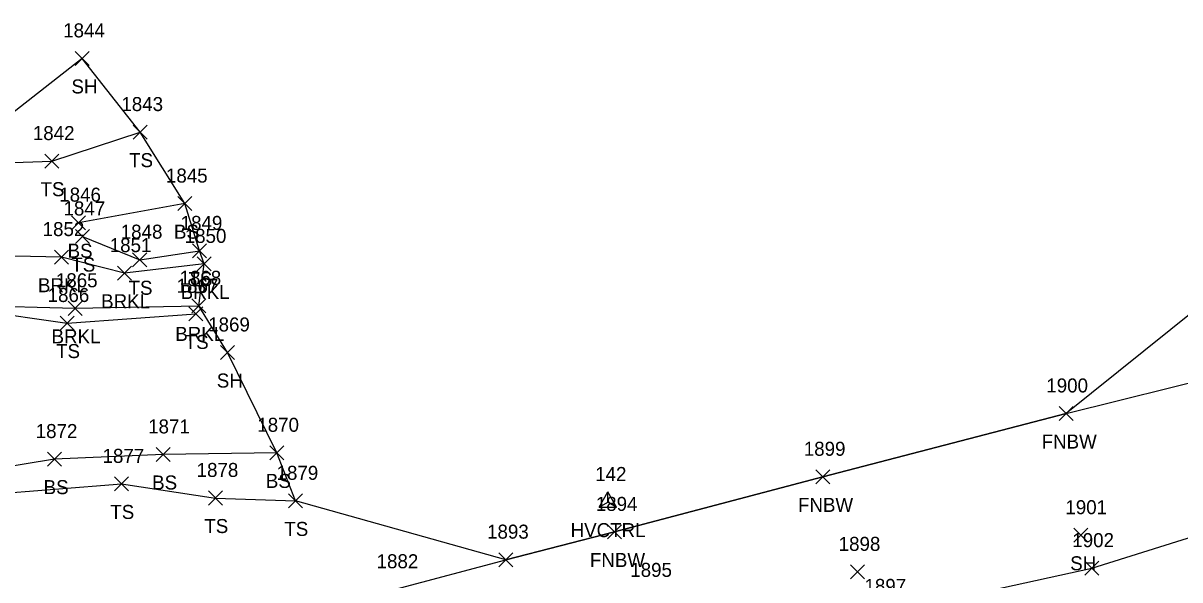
# Model space of a CAD drawing. Extents: x 1526508 to 1531550, y 369926 to 373082.
# Drawn here: x 1531169.1 to 1531334.3, y 370252.3 to 370331.7 of the extents above; entities that cross this region are included whole.
import ezdxf

# ---------------------------------------------------------------- set-up
doc = ezdxf.new("R2010")
doc.units = 0
for name, color, linetype in [('C_A', 7, 'Continuous'), ('C_I', 7, 'Continuous'), ('CPSM', 7, 'Continuous'), ('L_A', 7, 'Continuous'), ('L_I', 7, 'Continuous'), ('L_TIC', 7, 'Continuous'), ('LAWE', 7, 'Continuous'), ('LELB', 7, 'Continuous'), ('LFNC', 7, 'Continuous'), ('LSOGP', 7, 'Continuous')]:
    doc.layers.add(name, color=color, linetype=linetype)

msp = doc.modelspace()

# ---------------------------------------------------------------- linework, layer by layer
at = {"layer": 'CPSM'}
for p, q in [((1531251.34, 370262.68), (1531252.59, 370264.85)), ((1531253.84, 370262.68), (1531252.59, 370264.85)), ((1531252.59, 370263.4), (1531252.59, 370264.85)), ((1531251.34, 370262.68), (1531252.59, 370263.4)), ((1531251.34, 370262.68), (1531253.84, 370262.68)), ((1531252.59, 370263.4), (1531252.59, 370263.4)), ((1531252.59, 370263.4), (1531253.84, 370262.68))]:
    msp.add_line(p, q, dxfattribs=at)
at = {"layer": 'L_TIC'}
for points in [[(1531176.54, 370325.67), (1531178.54, 370327.67)], [(1531178.54, 370325.67), (1531176.54, 370327.67)], [(1531184.85, 370315.16), (1531186.85, 370317.16)], [(1531186.85, 370315.16), (1531184.85, 370317.16)], [(1531172.21, 370311.02), (1531174.21, 370313.02)], [(1531174.21, 370311.02), (1531172.21, 370313.02)], [(1531191.22, 370304.96), (1531193.22, 370306.96)], [(1531193.22, 370304.96), (1531191.22, 370306.96)], [(1531176.04, 370302.24), (1531178.04, 370304.24)], [(1531178.04, 370302.24), (1531176.04, 370304.24)], [(1531176.6, 370300.27), (1531178.6, 370302.27)], [(1531178.6, 370300.27), (1531176.6, 370302.27)], [(1531193.32, 370298.21), (1531195.32, 370300.21)], [(1531195.32, 370298.21), (1531193.32, 370300.21)], [(1531173.61, 370297.33), (1531175.61, 370299.33)], [(1531175.61, 370297.33), (1531173.61, 370299.33)], [(1531184.77, 370296.96), (1531186.77, 370298.96)], [(1531186.77, 370296.96), (1531184.77, 370298.96)], [(1531193.98, 370296.36), (1531195.98, 370298.36)], [(1531195.98, 370296.36), (1531193.98, 370298.36)], [(1531182.62, 370295.04), (1531184.62, 370297.04)], [(1531184.62, 370295.04), (1531182.62, 370297.04)], [(1531175.55, 370290.03), (1531177.55, 370292.03)], [(1531177.55, 370290.03), (1531175.55, 370292.03)], [(1531193.2, 370290.38), (1531195.2, 370292.38)], [(1531195.2, 370290.38), (1531193.2, 370292.38)], [(1531192.79, 370289.24), (1531194.79, 370291.24)], [(1531194.79, 370289.24), (1531192.79, 370291.24)], [(1531174.43, 370287.93), (1531176.43, 370289.93)], [(1531176.43, 370287.93), (1531174.43, 370289.93)], [(1531197.29, 370283.73), (1531199.29, 370285.73)], [(1531199.29, 370283.73), (1531197.29, 370285.73)], [(1531317.04, 370275.03), (1531319.04, 370277.03)], [(1531319.04, 370275.03), (1531317.04, 370277.03)], [(1531172.62, 370268.53), (1531174.62, 370270.53)], [(1531174.62, 370268.53), (1531172.62, 370270.53)], [(1531188.11, 370269.19), (1531190.11, 370271.19)], [(1531190.11, 370269.19), (1531188.11, 370271.19)], [(1531204.34, 370269.42), (1531206.34, 370271.42)], [(1531206.34, 370269.42), (1531204.34, 370271.42)], [(1531182.17, 370264.99), (1531184.17, 370266.99)], [(1531184.17, 370264.99), (1531182.17, 370266.99)], [(1531282.27, 370266), (1531284.27, 370268)], [(1531284.27, 370266), (1531282.27, 370268)], [(1531195.59, 370262.98), (1531197.59, 370264.98)], [(1531197.59, 370262.98), (1531195.59, 370264.98)], [(1531207.01, 370262.57), (1531209.01, 370264.57)], [(1531209.01, 370262.57), (1531207.01, 370264.57)], [(1531252.57, 370258.14), (1531254.57, 370260.14)], [(1531254.57, 370258.14), (1531252.57, 370260.14)], [(1531319.12, 370257.67), (1531321.12, 370259.67)], [(1531321.12, 370257.67), (1531319.12, 370259.67)], [(1531237.05, 370254.18), (1531239.05, 370256.18)], [(1531239.05, 370254.18), (1531237.05, 370256.18)], [(1531287.24, 370252.44), (1531289.24, 370254.44)], [(1531289.24, 370252.44), (1531287.24, 370254.44)], [(1531320.67, 370252.97), (1531322.67, 370254.97)], [(1531322.67, 370252.97), (1531320.67, 370254.97)]]:
    msp.add_lwpolyline(points, dxfattribs=at)
at = {"layer": 'LAWE'}
for points in [[(1531194.98, 370297.36), (1531183.62, 370296.04), (1531174.61, 370298.33), (1531159.02, 370298.68), (1531147.38, 370293.08), (1531134.87, 370276.86), (1531127.51, 370263.61)], [(1531142, 370261.2), (1531149.62, 370274.59), (1531149.75, 370281.72), (1531162.12, 370291.45), (1531176.55, 370291.03), (1531194.2, 370291.38)]]:
    msp.add_lwpolyline(points, dxfattribs=at)
at = {"layer": 'LELB'}
for points in [[(1531144.65, 370206.06), (1531164.57, 370210.72), (1531180.3, 370218.31), (1531196.61, 370223.05), (1531216.18, 370227.2), (1531246.26, 370234.32), (1531259.5, 370237.9), (1531291.92, 370247.44), (1531321.67, 370253.97), (1531341.88, 370260.29), (1531377.42, 370272.37), (1531403.24, 370281.83), (1531425.1, 370287.02), (1531443.59, 370293.1), (1531470.33, 370300.31), (1531494.61, 370309.28), (1531517.9, 370316.82)], [(1531158.16, 370311.5), (1531173.21, 370312.02), (1531185.85, 370316.16)], [(1531192.22, 370305.96), (1531177.04, 370303.24)], [(1531177.6, 370301.27), (1531185.77, 370297.96), (1531194.32, 370299.21)], [(1531143.44, 370260.72), (1531150.84, 370273.11), (1531151.55, 370280.84), (1531162.78, 370290.73), (1531175.43, 370288.93), (1531193.79, 370290.24)], [(1531205.34, 370270.42), (1531189.11, 370270.19), (1531173.62, 370269.53), (1531161.15, 370267.49), (1531151.65, 370259.41)], [(1531153.64, 370256.21), (1531163.98, 370264.47), (1531183.17, 370265.99), (1531196.59, 370263.98), (1531208.01, 370263.57)]]:
    msp.add_lwpolyline(points, dxfattribs=at)
at = {"layer": 'LFNC'}
msp.add_lwpolyline([(1531134.08, 370228.63), (1531150.19, 370233.69), (1531175.89, 370240.05), (1531199.88, 370245.87), (1531222.28, 370250.96), (1531238.05, 370255.18), (1531253.57, 370259.14), (1531283.27, 370267), (1531318.04, 370276.03), (1531340.6, 370281.65), (1531362.15, 370285.77), (1531399.51, 370294.39), (1531422.47, 370298.84)], dxfattribs=at)
at = {"layer": 'LSOGP'}
msp.add_lwpolyline([(1531344.04, 370296.88), (1531318.04, 370276.03), (1531283.27, 370267), (1531253.57, 370259.14), (1531238.05, 370255.18), (1531208.01, 370263.57), (1531205.34, 370270.42), (1531198.29, 370284.73), (1531194.2, 370291.38), (1531194.98, 370297.36), (1531194.32, 370299.21), (1531192.22, 370305.96), (1531185.85, 370316.16), (1531177.54, 370326.67), (1531158.16, 370311.5)], dxfattribs=at)

# ---------------------------------------------------------------- texts
at = {"layer": 'C_A'}
msp.add_text('HVCTRL', height=2, dxfattribs=at).set_placement((1531247.28, 370258.4))
at = {"layer": 'C_I'}
msp.add_text('142', height=2, dxfattribs=at).set_placement((1531250.79, 370266.4))
at = {"layer": 'L_A'}
for s, p in [('SH', (1531176.03, 370321.67)), ('TS', (1531184.26, 370311.16)), ('TS', (1531171.62, 370307.02)), ('BS', (1531190.66, 370300.96)), ('BS', (1531175.48, 370298.24)), ('TS', (1531176.01, 370296.27)), ('BRKL', (1531171.25, 370293.33)), ('TS', (1531184.18, 370292.96)), ('TS', (1531192.73, 370294.21)), ('BRKL', (1531191.62, 370292.36)), ('BRKL', (1531180.27, 370291.04)), ('BRKL', (1531190.85, 370286.38)), ('BRKL', (1531173.19, 370286.03)), ('TS', (1531192.2, 370285.24)), ('TS', (1531173.84, 370283.93)), ('SH', (1531196.78, 370279.73)), ('FNBW', (1531314.52, 370271.03)), ('BS', (1531187.55, 370265.19)), ('BS', (1531203.78, 370265.42)), ('BS', (1531172.06, 370264.53)), ('FNBW', (1531279.74, 370262)), ('TS', (1531181.58, 370260.99)), ('TS', (1531195, 370258.98)), ('TS', (1531206.42, 370258.57)), ('FNBW', (1531250.04, 370254.14)), ('SH', (1531318.6, 370253.67))]:
    msp.add_text(s, height=2, dxfattribs=at).set_placement(p)
at = {"layer": 'L_I'}
for s, p in [('1844', (1531174.85, 370329.67)), ('1843', (1531183.16, 370319.16)), ('1842', (1531170.52, 370315.02)), ('1845', (1531189.52, 370308.96)), ('1846', (1531174.29, 370306.24)), ('1847', (1531174.9, 370304.27)), ('1852', (1531171.92, 370301.33)), ('1849', (1531191.62, 370302.21)), ('1848', (1531183.07, 370300.96)), ('1850', (1531192.2, 370300.36)), ('1851', (1531181.5, 370299.04)), ('1865', (1531173.81, 370294.03)), ('1867', (1531191.05, 370293.24)), ('1868', (1531191.46, 370294.38)), ('1866', (1531172.63, 370291.93)), ('1869', (1531195.55, 370287.73)), ('1900', (1531315.19, 370279.03)), ('1871', (1531186.98, 370273.19)), ('1870', (1531202.56, 370273.42)), ('1872', (1531170.93, 370272.53)), ('1899', (1531280.57, 370270)), ('1877', (1531180.47, 370268.99)), ('1878', (1531193.9, 370266.98)), ('1879', (1531205.31, 370266.57)), ('1894', (1531250.88, 370262.14)), ('1901', (1531317.91, 370261.67)), ('1893', (1531235.36, 370258.18)), ('1902', (1531318.9, 370256.97)), ('1898', (1531285.55, 370256.44)), ('1882', (1531219.59, 370253.96)), ('1895', (1531255.8, 370252.73)), ('1897', (1531289.23, 370250.44))]:
    msp.add_text(s, height=2, dxfattribs=at).set_placement(p)

doc.saveas('drawing.dxf')
